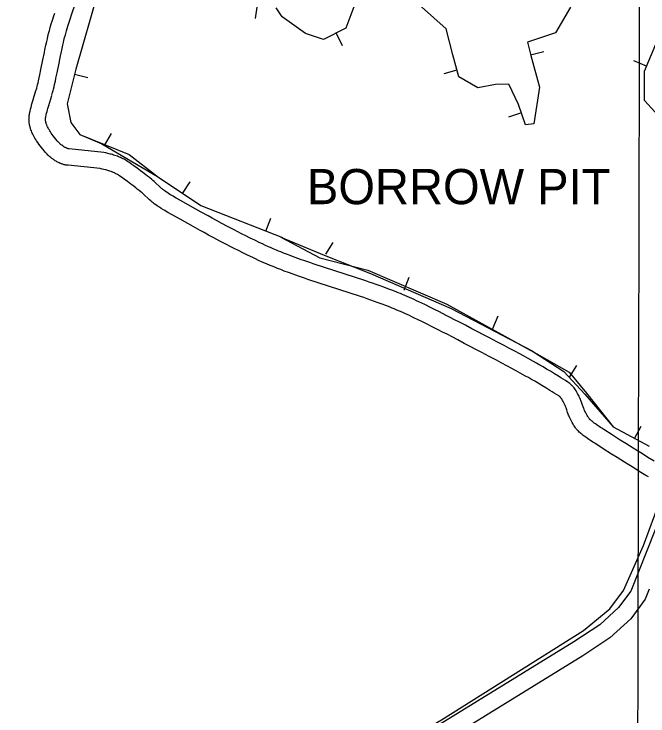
# Model space of a CAD drawing. Extents: x 3177185 to 3215018, y 812988 to 838321.
# Drawn here: x 3190722 to 3191874, y 831385 to 832662 of the extents above; entities that cross this region are included whole.
import ezdxf

# ---------------------------------------------------------------- set-up
doc = ezdxf.new("R2010")
doc.units = 0
for name, color, linetype in [('V-BORW-IDEN', 7, 'Continuous'), ('V-BORW-LINE', 7, 'Continuous'), ('V-GRID-MAJR', 7, 'Continuous'), ('V-ROAD-CNTR', 7, 'Continuous'), ('V-TOPO-SHOR', 7, 'Continuous')]:
    doc.layers.add(name, color=color, linetype=linetype)

msp = doc.modelspace()

# ---------------------------------------------------------------- linework, layer by layer
at = {"layer": 'V-BORW-LINE'}
for p, q in [((3191164.256, 832678.2880000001), (3191160.16, 832653.626)), ((3191307.399, 832626.823), (3191318.778, 832604.563)), ((3191660.927, 832587.321), (3191685.252, 832593.09)), ((3191871.562, 832566.676), (3191848.4960000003, 832576.318)), ((3190832.382, 832552.0800000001), (3190856.599, 832545.876)), ((3191527.1720000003, 832559.5700000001), (3191503.091, 832552.856)), ((3191644.364, 832482.107), (3191620.738, 832473.935)), ((3190886.741, 832422.549), (3190899.432, 832444.088)), ((3191028.65, 832335.38), (3191042.518, 832356.181)), ((3191179.749, 832266.836), (3191188.917, 832290.094)), ((3191288.985, 832224.621), (3191302.021, 832245.953)), ((3191431.421, 832159.351), (3191440.1350000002, 832182.783)), ((3191592.392, 832089.453), (3191602.093, 832112.4940000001)), ((3191731.373, 832001.0700000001), (3191744.824, 832022.143)), ((3191849.986, 831889.9), (3191861.799, 831911.933))]:
    msp.add_line(p, q, dxfattribs=at)
for points in [[(3190874.161, 832698.762), (3190834.7460000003, 832561.31), (3190818.614, 832498.339), (3190825.598, 832464.417), (3190842.023, 832442.28), (3190931.542, 832405.7660000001), (3190982.7800000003, 832365.961), (3191061.612, 832313.404), (3191210.011, 832254.907)], [(3190874.161, 832698.762), (3190834.7460000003, 832561.31), (3190818.614, 832498.339), (3190825.598, 832464.417), (3190842.023, 832442.28), (3190881.549, 832425.608), (3190982.7800000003, 832365.961), (3191061.612, 832313.404), (3191210.011, 832254.907)], [(3191341.791, 832679.184), (3191324.9080000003, 832635.773), (3191284.387, 832615.06), (3191251.863, 832626.109), (3191209.224, 832656.447), (3191198.414, 832672.616)], [(3191341.791, 832679.184), (3191324.9080000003, 832635.773), (3191284.387, 832615.06), (3191251.863, 832626.109), (3191209.224, 832656.447), (3191198.414, 832672.616)], [(3191733.339, 832673.942), (3191706.0500000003, 832627.348), (3191655.474, 832610.317), (3191661.215, 832586.106), (3191677.063, 832528.4550000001), (3191667.102, 832462.012), (3191651.911, 832460.2880000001), (3191639.241, 832496.919), (3191621.091, 832534.248), (3191597.438, 832533.361), (3191564.8340000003, 832527), (3191530.5810000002, 832547.345), (3191519.4390000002, 832587.305), (3191507.677, 832634.479), (3191462.548, 832674.807)], [(3191733.339, 832673.942), (3191706.0500000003, 832627.348), (3191655.474, 832610.317), (3191661.215, 832586.106), (3191677.063, 832528.4550000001), (3191667.102, 832462.012), (3191651.911, 832460.2880000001), (3191639.241, 832496.919), (3191621.091, 832534.248), (3191597.438, 832533.361), (3191564.8340000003, 832527), (3191530.5810000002, 832547.345), (3191519.4390000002, 832587.305), (3191507.677, 832634.479), (3191462.548, 832674.807)], [(3191923.9390000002, 832442.637), (3191867.933, 832504.127), (3191867.828, 832557.7440000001), (3191908.8140000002, 832655.797)], [(3191923.9390000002, 832442.637), (3191867.933, 832504.127), (3191867.828, 832557.7440000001), (3191908.8140000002, 832655.797)], [(3191207.225, 832256.005), (3191277.987, 832218.24), (3191365.393, 832195.992), (3191508.421, 832134.013), (3191672.108, 832043.4280000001), (3191730.909, 832010.055), (3191762.693, 831971.915), (3191810.681, 831910.975), (3191876.345, 831875.767)], [(3191207.225, 832256.005), (3191285.933, 832223.008), (3191370.161, 832189.635), (3191516.367, 832126.067), (3191662.573, 832049.785), (3191721.373, 832011.645), (3191759.514, 831970.3250000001), (3191810.681, 831910.975), (3191876.345, 831875.767)]]:
    msp.add_lwpolyline(points, dxfattribs=at)
at = {"layer": 'V-GRID-MAJR'}
msp.add_spline([(3191823.847, 818374.883), (3191838.828, 824434.0750000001), (3191853.818, 830496.351), (3191868.808, 836558.667), (3191868.816, 836561.711)], degree=3, dxfattribs=at)
at = {"layer": 'V-ROAD-CNTR'}
for points in [[(3190790.8813813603, 832513.8129449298), (3190792.254378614, 832518.579935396), (3190793.270376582, 832522.25292805), (3190794.01637509, 832525.0609224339), (3190795.077372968, 832529.253914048), (3190796.0613710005, 832533.466905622), (3190797.335368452, 832539.2678940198), (3190798.4873661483, 832544.6778832), (3190800.5633619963, 832554.7588630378), (3190804.0673549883, 832572.3198279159), (3190806.700349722, 832585.423801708), (3190807.699347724, 832590.2677920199), (3190809.505344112, 832598.7677750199), (3190810.907341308, 832605.085762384), (3190811.9933391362, 832609.7987529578), (3190812.824337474, 832613.2977459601), (3190814.120334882, 832618.559735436), (3190815.4713321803, 832623.7947249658), (3190816.110330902, 832626.1747202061), (3190817.433328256, 832630.8877107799), (3190818.729325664, 832635.281701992), (3190819.994323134, 832639.406693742), (3190821.2183206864, 832643.2776859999), (3190822.392318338, 832646.8956787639), (3190824.6833137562, 832653.7616650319), (3190826.73630965, 832659.7676530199), (3190834.1362948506, 832681.0896103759)], [(3190762.0534390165, 832522.11292833), (3190763.382436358, 832526.729919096), (3190764.3164344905, 832530.1049123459), (3190764.9764331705, 832532.588907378), (3190765.925431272, 832536.345899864), (3190766.803429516, 832540.0988923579), (3190768.013427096, 832545.6078813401), (3190769.1234248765, 832550.825870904), (3190771.1614208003, 832560.720851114), (3190774.65141382, 832578.2098161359), (3190777.302408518, 832591.4077897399), (3190778.3354064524, 832596.4157797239), (3190780.189402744, 832605.135762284), (3190781.6453998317, 832611.7017491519), (3190782.78139756, 832616.63273929), (3190783.664395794, 832620.3517318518), (3190785.030393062, 832625.895720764), (3190786.459390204, 832631.4327096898), (3190787.180388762, 832634.1187043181), (3190788.6033859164, 832639.1856941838), (3190789.9993831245, 832643.9216847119), (3190791.350380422, 832648.3266759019), (3190792.6483778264, 832652.4316676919), (3190793.89637533, 832656.273660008), (3190796.259370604, 832663.3616458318)], [(3190820.6783217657, 832386.3791997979), (3190819.9443232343, 832386.416199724), (3190818.240326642, 832386.5851993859), (3190816.614329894, 832386.8211989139), (3190815.0723329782, 832387.111198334), (3190813.609335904, 832387.4421976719), (3190812.2113387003, 832387.80819694), (3190810.885341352, 832388.2011961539), (3190809.618343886, 832388.614195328), (3190808.398346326, 832389.049194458), (3190807.235348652, 832389.4961935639), (3190806.062350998, 832389.9771926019), (3190804.0273550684, 832390.884190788), (3190802.0773589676, 832391.84318887), (3190800.288362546, 832392.796186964), (3190798.6433658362, 832393.734185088), (3190797.1193688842, 832394.6551832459), (3190795.7143716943, 832395.5501814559), (3190794.41637429, 832396.416179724), (3190793.1613768, 832397.2901779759), (3190791.01638109, 832398.869174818), (3190789.13638485, 832400.3471718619), (3190787.53138806, 832401.6781692), (3190786.158390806, 832402.87316681), (3190784.972393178, 832403.94816466), (3190783.9203952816, 832404.9401626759), (3190782.257398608, 832406.5791593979), (3190781.002401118, 832407.885156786), (3190780.0494030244, 832408.917154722), (3190778.734405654, 832410.4091517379), (3190777.5004081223, 832411.8901487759), (3190774.6084139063, 832415.497141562), (3190771.9644191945, 832418.86313483), (3190769.51642409, 832422.0701284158), (3190767.262428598, 832425.1271223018), (3190765.2014327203, 832428.039116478), (3190763.3234364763, 832430.81311093), (3190761.6184398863, 832433.461105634), (3190760.075442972, 832435.990100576), (3190758.6874457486, 832438.4010957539), (3190757.443448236, 832440.7000911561), (3190756.33145046, 832442.8940867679), (3190755.342452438, 832444.9860825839), (3190754.4654541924, 832446.9780785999), (3190753.690455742, 832448.880074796), (3190753.0104571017, 832450.6900711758), (3190752.4174582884, 832452.40806774), (3190751.9024593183, 832454.037064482), (3190751.453460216, 832455.59306137), (3190751.0704609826, 832457.06805842), (3190750.742461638, 832458.4660556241), (3190750.4674621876, 832459.7820529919), (3190750.2194626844, 832461.109050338), (3190749.87146338, 832463.3940457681), (3190749.6394638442, 832465.494041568), (3190749.5034641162, 832467.3640378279), (3190749.440464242, 832469.0040345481), (3190749.4264642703, 832470.4530316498), (3190749.450464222, 832471.81302893), (3190749.560464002, 832473.9380246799), (3190749.7154636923, 832475.6360212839), (3190749.878463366, 832476.986018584), (3190750.1644627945, 832478.8450148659), (3190750.518462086, 832480.6840111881), (3190751.418460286, 832484.7190031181), (3190752.310458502, 832488.4119957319), (3190753.192456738, 832491.8419888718), (3190754.049455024, 832495.026982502), (3190754.88145336, 832498.011976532), (3190756.469450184, 832503.489965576), (3190762.099438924, 832522.269928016)], [(3190822.17631877, 832416.3421398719), (3190821.880319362, 832416.3711398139), (3190821.540320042, 832416.4211397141), (3190821.152320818, 832416.49313957), (3190820.725321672, 832416.590139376), (3190820.2753225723, 832416.7081391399), (3190819.799323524, 832416.8491388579), (3190819.3063245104, 832417.010138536), (3190818.8143254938, 832417.185138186), (3190818.3113265, 832417.3781378), (3190817.86632739, 832417.561137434), (3190816.7553296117, 832418.0561364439), (3190815.7513316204, 832418.549135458), (3190814.7743335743, 832419.0701344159), (3190813.833335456, 832419.606133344), (3190812.945337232, 832420.1431322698), (3190812.104338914, 832420.680131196), (3190811.312340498, 832421.2081301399), (3190810.625341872, 832421.686129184), (3190809.180344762, 832422.7491270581), (3190807.98634715, 832423.6871251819), (3190806.9593492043, 832424.5401234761), (3190806.082350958, 832425.3031219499), (3190805.3403524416, 832425.9761206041), (3190804.744353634, 832426.5381194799), (3190803.607355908, 832427.659117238), (3190802.840357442, 832428.4571156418), (3190802.323358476, 832429.017114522), (3190801.51636009, 832429.9311126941), (3190800.732361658, 832430.8741108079), (3190798.10636691, 832434.1471042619), (3190795.684371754, 832437.231098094), (3190793.514376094, 832440.074092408), (3190791.582379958, 832442.6950871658), (3190789.8693833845, 832445.115082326), (3190788.359386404, 832447.347077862), (3190787.03638905, 832449.3990737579), (3190785.885391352, 832451.286069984), (3190784.8853933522, 832453.0250665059), (3190784.019395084, 832454.624063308), (3190783.275396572, 832456.0920603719), (3190782.6363978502, 832457.4420576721), (3190782.09139894, 832458.6820551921), (3190781.628399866, 832459.8180529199), (3190781.23640065, 832460.862050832), (3190780.903401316, 832461.826048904), (3190780.622401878, 832462.7150471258), (3190780.3894023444, 832463.5250455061), (3190780.194402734, 832464.2720440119), (3190780.032403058, 832464.9620426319), (3190779.897403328, 832465.6080413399), (3190779.80140352, 832466.121040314), (3190779.6234038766, 832467.2980379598), (3190779.5194040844, 832468.234036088), (3190779.4614042, 832469.0300344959), (3190779.434404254, 832469.7280330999), (3190779.428404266, 832470.331031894), (3190779.43640425, 832470.7670310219), (3190779.490404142, 832471.79802896), (3190779.5514040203, 832472.472027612), (3190779.604403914, 832472.9060267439), (3190779.730403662, 832473.731025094), (3190779.8944033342, 832474.582023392), (3190780.640401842, 832477.9310166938), (3190781.420400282, 832481.154010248), (3190782.204398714, 832484.20800414), (3190782.983397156, 832487.0969983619), (3190783.739395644, 832489.80799294), (3190785.245392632, 832495.00798254), (3190790.835381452, 832513.6559452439)], [(3191074.844813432, 832294.302383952), (3191062.266838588, 832301.2573700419), (3191052.872857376, 832306.49335957), (3191038.771885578, 832314.4123437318), (3191024.6719137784, 832322.3833277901), (3191016.707929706, 832326.904318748), (3191013.799935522, 832328.5803153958), (3191011.283940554, 832330.0503124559), (3191009.14094484, 832331.3263099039), (3191005.378952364, 832333.6243053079), (3191002.647957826, 832335.355301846), (3191000.63596185, 832336.672299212), (3190999.176964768, 832337.6512972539), (3190996.9679691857, 832339.179294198), (3190994.837973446, 832340.7112911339), (3190993.58097596, 832341.661289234), (3190992.424978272, 832342.5782874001), (3190991.333980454, 832343.481285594), (3190990.329982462, 832344.342283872), (3190988.3079865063, 832346.1402802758), (3190986.5609899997, 832347.7522770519), (3190979.944003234, 832354.01326453), (3190978.1570068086, 832355.670261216), (3190976.7410096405, 832356.955258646), (3190974.592013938, 832358.8442548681), (3190972.387018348, 832360.69325117), (3190968.359026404, 832363.9472446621), (3190964.864033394, 832366.726239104), (3190961.7800395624, 832369.1452342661), (3190956.4010503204, 832373.294225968), (3190952.309058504, 832376.395219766), (3190946.1660707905, 832380.966210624), (3190939.972083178, 832385.4862015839), (3190936.5870899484, 832387.9211967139), (3190933.539096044, 832390.071192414), (3190930.774101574, 832391.959188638), (3190928.272106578, 832393.6021853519), (3190926.0161110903, 832395.0201825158), (3190923.985115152, 832396.241180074), (3190922.15611881, 832397.2901779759), (3190920.5201220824, 832398.186176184), (3190919.063124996, 832398.9501746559), (3190917.7081277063, 832399.6311732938), (3190915.4461322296, 832400.700171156), (3190913.6491358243, 832401.4911695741), (3190912.217138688, 832402.0821683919), (3190910.15114282, 832402.875166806), (3190908.0651469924, 832403.6021653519), (3190905.600151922, 832404.3961637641), (3190903.2731565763, 832405.1101623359), (3190901.027161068, 832405.7671610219), (3190898.85616541, 832406.375159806), (3190896.717169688, 832406.9501586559), (3190892.695177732, 832407.96815662), (3190888.9051853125, 832408.861154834), (3190885.3691923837, 832409.645153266), (3190822.17631877, 832416.3421398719)], [(3191060.33084246, 832268.0484364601), (3191047.704867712, 832275.027422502), (3191038.224886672, 832280.3134119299), (3191024.04591503, 832288.276396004), (3191009.88594335, 832296.2813799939), (3191001.81595949, 832300.862370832), (3190998.741965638, 832302.632367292), (3190996.043971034, 832304.210364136), (3190993.648975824, 832305.6343612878), (3190989.526984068, 832308.1543562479), (3190986.403990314, 832310.1333522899), (3190984.0639949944, 832311.6643492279), (3190982.2829985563, 832312.859346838), (3190979.6740037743, 832314.6653432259), (3190977.040009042, 832316.559339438), (3190975.2110127, 832317.939336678), (3190973.53101606, 832319.274334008), (3190972.010019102, 832320.53333149), (3190970.600021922, 832321.7403290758), (3190968.168026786, 832323.9043247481), (3190966.08103096, 832325.8283209), (3190959.4320442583, 832332.1193083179), (3190957.873047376, 832333.566305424), (3190956.755049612, 832334.5813033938), (3190955.050053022, 832336.080300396), (3190953.32105648, 832337.529297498), (3190949.5970639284, 832340.5392914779), (3190946.2720705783, 832343.182286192), (3190943.362076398, 832345.465281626), (3190938.18108676, 832349.4602736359), (3190934.295094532, 832352.405267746), (3190928.370106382, 832356.8142589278), (3190922.370118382, 832361.1922501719), (3190919.1811247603, 832363.4872455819), (3190916.435130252, 832365.4232417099), (3190914.080134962, 832367.031238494), (3190912.0541390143, 832368.362235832), (3190910.3041425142, 832369.4622336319), (3190908.7911455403, 832370.3712318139), (3190907.48614815, 832371.120230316), (3190906.350150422, 832371.7422290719), (3190905.3611524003, 832372.260228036), (3190904.55615401, 832372.665227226), (3190902.994157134, 832373.4042257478), (3190901.8851593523, 832373.891224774), (3190901.1131608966, 832374.2102241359), (3190899.835163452, 832374.7012231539), (3190898.529166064, 832375.156222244), (3190896.6041699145, 832375.7762210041), (3190894.665173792, 832376.370219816), (3190892.767177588, 832376.9252187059), (3190890.914181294, 832377.445217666), (3190889.145184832, 832377.9202167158), (3190885.573191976, 832378.824214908), (3190882.219198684, 832379.615213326), (3190879.039205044, 832380.3192119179), (3190820.6783217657, 832386.3791997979)], [(3191736.655489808, 831985.377001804), (3191735.8594914, 831986.212000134), (3191734.3304944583, 831987.695997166), (3191733.030497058, 831988.849994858), (3191731.92949926, 831989.757993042), (3191730.366502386, 831990.9429906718), (3191728.813505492, 831992.000988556), (3191724.272514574, 831994.9099827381), (3191720.0115230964, 831997.60897734), (3191715.878531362, 832000.1989721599), (3191711.857539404, 832002.690967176), (3191704.09955492, 832007.4359576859), (3191696.798569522, 832011.8229489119), (3191689.94458323, 832015.8779408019), (3191683.511596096, 832019.6319332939), (3191677.4716081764, 832023.112926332), (3191671.80461951, 832026.3439198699), (3191666.476630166, 832029.3539138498), (3191656.503650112, 832034.9149027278), (3191647.7526676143, 832039.7268931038), (3191640.0866829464, 832043.899884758), (3191633.363696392, 832047.527877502), (3191621.6097199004, 832053.814864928), (3191612.767737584, 832058.505855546), (3191599.49976412, 832065.502841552), (3191586.210790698, 832072.4818275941), (3191554.421854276, 832089.1977941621), (3191542.4878781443, 832095.4587816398), (3191532.027899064, 832100.922770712), (3191522.8579174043, 832105.686761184), (3191514.8189334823, 832109.836752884), (3191507.7629475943, 832113.4567456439), (3191495.4069723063, 832119.7357330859), (3191486.09999092, 832124.4077237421), (3191479.089004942, 832127.8907167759), (3191468.57002598, 832133.0497064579), (3191463.273036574, 832135.6147013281), (3191457.961047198, 832138.165696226), (3191453.5870559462, 832140.23369209), (3191449.251064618, 832142.240688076), (3191444.974073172, 832144.1796841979), (3191440.754081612, 832146.0576804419), (3191436.5910899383, 832147.8736768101), (3191432.48509815, 832149.63367329), (3191428.432106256, 832151.339669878), (3191424.438114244, 832152.991666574), (3191420.5021221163, 832154.5956633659), (3191416.602129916, 832156.15866024), (3191408.9601451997, 832159.1556542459), (3191401.519160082, 832161.9916485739), (3191394.299174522, 832164.676643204), (3191387.2901885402, 832167.224638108), (3191380.491202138, 832169.6446332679), (3191373.898215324, 832171.9496286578), (3191367.5042281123, 832174.14862426), (3191361.248240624, 832176.2696200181), (3191265.588431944, 832207.4305576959), (3191259.744443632, 832209.40855374), (3191254.229454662, 832211.2975499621), (3191249.074464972, 832213.087546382), (3191244.251474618, 832214.7855429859), (3191239.758483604, 832216.3875397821), (3191231.321500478, 832219.4585336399), (3191223.988515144, 832222.197528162), (3191217.602527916, 832224.6425232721), (3191212.04053904, 832226.821518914), (3191207.19054874, 832228.761515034), (3191202.9615571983, 832230.4845115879), (3191199.292564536, 832232.0055085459), (3191192.842577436, 832234.739503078), (3191188.048587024, 832236.824498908), (3191184.484594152, 832238.405495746), (3191179.1226048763, 832240.8364908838), (3191173.7766155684, 832243.324485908), (3191169.062624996, 832245.5604814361), (3191159.87564337, 832249.9824725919), (3191151.303660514, 832254.1824641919), (3191143.2906765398, 832258.1714562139), (3191135.799691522, 832261.952448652), (3191128.79070554, 832265.5344414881), (3191122.23071866, 832268.92343471), (3191116.092730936, 832272.124428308), (3191110.3567424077, 832275.1414222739), (3191099.5887639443, 832280.86841082), (3191090.1957827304, 832285.926400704), (3191081.9867991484, 832290.389391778), (3191074.79581353, 832294.3303838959)], [(3191714.9435332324, 831964.675043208), (3191714.54953402, 831965.088042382), (3191713.916535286, 831965.7020411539), (3191713.52453607, 831966.050040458), (3191713.3155364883, 831966.222040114), (3191712.8425374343, 831966.5810393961), (3191712.271538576, 831966.9710386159), (3191708.1565468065, 831969.6060333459), (3191704.0215550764, 831972.2250281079), (3191700.0085631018, 831974.7390230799), (3191696.1275708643, 831977.1470182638), (3191688.5475860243, 831981.7820089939), (3191681.4346002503, 831986.055000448), (3191674.746613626, 831990.0119925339), (3191668.4596262, 831993.6799851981), (3191662.5516380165, 831997.0869783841), (3191656.998649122, 832000.251972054), (3191651.792659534, 832003.1919661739), (3191641.96967918, 832008.6709552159), (3191633.3546964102, 832013.40894574), (3191625.792711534, 832017.52393751), (3191619.1657247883, 832021.099930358), (3191607.5037481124, 832027.3369178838), (3191598.7397656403, 832031.987908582), (3191585.5277920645, 832038.9548946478), (3191572.2548186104, 832045.9258807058), (3191540.471882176, 832062.637847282), (3191528.5739059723, 832068.880834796), (3191518.167926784, 832074.3168239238), (3191509.061944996, 832079.0468144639), (3191501.090960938, 832083.162806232), (3191494.1209748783, 832086.7387990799), (3191481.882999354, 832092.9577866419), (3191472.6980177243, 832097.567777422), (3191465.811031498, 832100.9887705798), (3191455.426052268, 832106.0817603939), (3191450.243062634, 832108.592755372), (3191445.0570730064, 832111.0817503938), (3191440.8730813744, 832113.059746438), (3191436.7550896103, 832114.9667426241), (3191432.682097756, 832116.81373893), (3191428.658105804, 832118.60373535), (3191424.6831137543, 832120.3377318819), (3191420.75512161, 832122.021728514), (3191416.878129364, 832123.65372525), (3191413.0461370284, 832125.2397220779), (3191409.2621445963, 832126.779718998), (3191405.544152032, 832128.2707160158), (3191398.14016684, 832131.1737102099), (3191390.949181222, 832133.915704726), (3191383.9471952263, 832136.5186995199), (3191377.136208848, 832138.994694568), (3191370.5112220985, 832141.352689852), (3191364.068234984, 832143.605685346), (3191357.8082475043, 832145.75868104), (3191351.784259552, 832147.801676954), (3191256.134450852, 832178.95861464), (3191250.074462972, 832181.00861054), (3191244.4454742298, 832182.9376066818), (3191239.172484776, 832184.7696030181), (3191234.2334946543, 832186.5075995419), (3191229.5905039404, 832188.1635962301), (3191220.9415212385, 832191.310589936), (3191213.376536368, 832194.137584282), (3191206.768549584, 832196.6665792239), (3191200.996561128, 832198.9275747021), (3191195.9585712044, 832200.9435706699), (3191191.5575800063, 832202.7365670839), (3191187.694587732, 832204.3375638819), (3191181.0066011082, 832207.1735582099), (3191175.984611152, 832209.356553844), (3191172.2086187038, 832211.031550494), (3191166.598629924, 832213.574545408), (3191161.0186410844, 832216.1725402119), (3191156.128650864, 832218.4905355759), (3191146.769669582, 832222.9965265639), (3191138.019687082, 832227.284517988), (3191129.848703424, 832231.3515098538), (3191122.213718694, 832235.204502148), (3191115.0807329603, 832238.8504948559), (3191108.4107463, 832242.2954879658), (3191102.172758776, 832245.5484814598), (3191096.328770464, 832248.6234753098), (3191085.432792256, 832254.4184637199), (3191075.917811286, 832259.5424534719), (3191067.6148278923, 832264.0574444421), (3191060.379842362, 832268.020436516)], [(3191885.6221918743, 831848.2522760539), (3191874.137214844, 831855.276262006), (3191864.0432350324, 831861.503249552), (3191855.225252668, 831866.9832385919), (3191847.5252680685, 831871.7972289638), (3191834.0512950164, 831880.2822119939), (3191823.970315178, 831886.6741992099), (3191808.8523454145, 831896.327179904), (3191793.753375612, 831906.038160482), (3191790.575381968, 831908.0961563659), (3191787.8453874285, 831909.8871527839), (3191785.497392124, 831911.4521496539), (3191783.477396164, 831912.8211469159), (3191781.763399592, 831914.0071445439), (3191778.733405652, 831916.1601402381), (3191776.538410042, 831917.777137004), (3191774.9504132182, 831918.9831345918), (3191772.5084181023, 831920.90413075), (3191771.363420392, 831921.8371288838), (3191770.305422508, 831922.7181271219), (3191769.617423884, 831923.3291259), (3191769.0894249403, 831923.843124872), (3191768.598425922, 831924.362123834), (3191768.127426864, 831924.8971227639), (3191767.683427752, 831925.4341216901), (3191767.268428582, 831925.9651206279), (3191766.9144292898, 831926.4411196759), (3191766.110430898, 831927.595117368), (3191765.4464322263, 831928.6181153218), (3191764.883433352, 831929.5311134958), (3191763.7894355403, 831931.4151097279), (3191763.006437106, 831932.8301068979), (3191760.463442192, 831937.6130973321), (3191759.7074437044, 831939.108094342), (3191759.0864449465, 831940.4470916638), (3191758.515446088, 831941.777089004), (3191757.986447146, 831943.086086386), (3191757.5114480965, 831944.3250839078), (3191756.5794499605, 831946.8970787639), (3191754.9064533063, 831951.77406901), (3191753.556456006, 831955.6640612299), (3191752.422458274, 831958.742055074), (3191751.4744601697, 831961.137050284), (3191750.6964617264, 831962.9760466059), (3191750.0484630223, 831964.4250437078), (3191749.052465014, 831966.5140395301), (3191747.988467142, 831968.567035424), (3191746.438470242, 831971.395029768), (3191745.0054731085, 831973.8980247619), (3191743.628475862, 831976.16902022), (3191742.310478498, 831978.2000161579), (3191741.060480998, 831979.998012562), (3191739.8794833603, 831981.583009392), (3191738.770485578, 831982.97400661), (3191737.740487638, 831984.18400419), (3191736.932489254, 831985.0790023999)], [(3191874.895213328, 831819.8373328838), (3191872.518218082, 831821.15433025), (3191870.186222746, 831822.5283275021), (3191858.4352462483, 831829.712313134), (3191848.2492666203, 831835.9973005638), (3191839.355284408, 831841.5252895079), (3191831.5812999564, 831846.385279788), (3191818.0253270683, 831854.920262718), (3191807.8643473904, 831861.36424983), (3191792.666377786, 831871.0692304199), (3191777.485408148, 831880.8322108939), (3191774.193414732, 831882.96420663), (3191771.301420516, 831884.861202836), (3191768.7594256, 831886.5541994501), (3191766.527430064, 831888.06919642), (3191764.541434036, 831889.441193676), (3191761.147440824, 831891.8541888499), (3191758.568445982, 831893.753185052), (3191756.602449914, 831895.2471820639), (3191753.760455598, 831897.482177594), (3191752.285458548, 831898.6831751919), (3191750.737461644, 831899.9741726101), (3191749.1934647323, 831901.345169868), (3191747.727467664, 831902.7691670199), (3191746.4344702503, 831904.1361642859), (3191745.3014725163, 831905.4231617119), (3191744.2954745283, 831906.640159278), (3191743.398476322, 831907.78915698), (3191742.5604779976, 831908.9191547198), (3191741.218480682, 831910.843150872), (3191740.090482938, 831912.580147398), (3191739.13948484, 831914.1251443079), (3191737.691487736, 831916.6151393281), (3191736.63448985, 831918.5261355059), (3191733.8294954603, 831923.8011249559), (3191732.705497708, 831926.0241205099), (3191731.688499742, 831928.2171161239), (3191730.821501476, 831930.2371120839), (3191730.0705029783, 831932.0941083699), (3191729.39950432, 831933.8451048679), (3191728.285506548, 831936.9190987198), (3191726.546510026, 831941.990088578), (3191725.3085125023, 831945.5580814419), (3191724.39451433, 831948.0360764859), (3191723.7085157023, 831949.7730730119), (3191723.186516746, 831951.0060705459), (3191722.8125174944, 831951.843068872), (3191722.186518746, 831953.1540662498), (3191721.512520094, 831954.457063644), (3191720.26452259, 831956.7330590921), (3191719.157524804, 831958.668055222), (3191718.21452669, 831960.2230521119), (3191717.406528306, 831961.4680496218), (3191716.712529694, 831962.466047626), (3191716.11953088, 831963.261046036), (3191715.61453189, 831963.89404477), (3191715.1805327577, 831964.40404375), (3191714.666533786, 831964.9730426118)], [(3191916.187130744, 831796.9353786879), (3191842.9722771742, 831611.866748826), (3191820.698321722, 831581.9968085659), (3191786.66438979, 831550.6308712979), (3191739.783483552, 831519.6899331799), (3191298.209366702, 831247.644477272), (3191057.9088473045, 831111.6427492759)], [(3191876.6592098, 831615.470741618), (3191869.4022243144, 831597.126778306), (3191843.080276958, 831561.8268489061), (3191805.212352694, 831526.9269187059), (3191755.917451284, 831494.393983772), (3191313.471336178, 831221.8105289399), (3191072.684817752, 831085.534801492)]]:
    msp.add_lwpolyline(points, dxfattribs=at)
at = {"layer": 'V-TOPO-SHOR'}
msp.add_lwpolyline([(3189873.126, 830517.04), (3190093.4844725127, 830628.818769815), (3190654.520692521, 830912.1420609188), (3190845.2730073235, 831004.7130372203), (3190999.5579678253, 831086.0632891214), (3191498.8802036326, 831377.8021235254), (3191756.956864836, 831540.5026273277), (3191804.6449435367, 831579.7751627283), (3191829.8915734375, 831613.4373359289), (3191866.358927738, 831694.7875878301), (3191897.215919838, 831778.9430208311)], dxfattribs=at)

# ---------------------------------------------------------------- texts
at = {"layer": 'V-BORW-IDEN'}
msp.add_text('BORROW PIT', height=64.000002, dxfattribs=at).set_placement((3191254.460298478, 832315.704903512))

doc.saveas('drawing.dxf')
